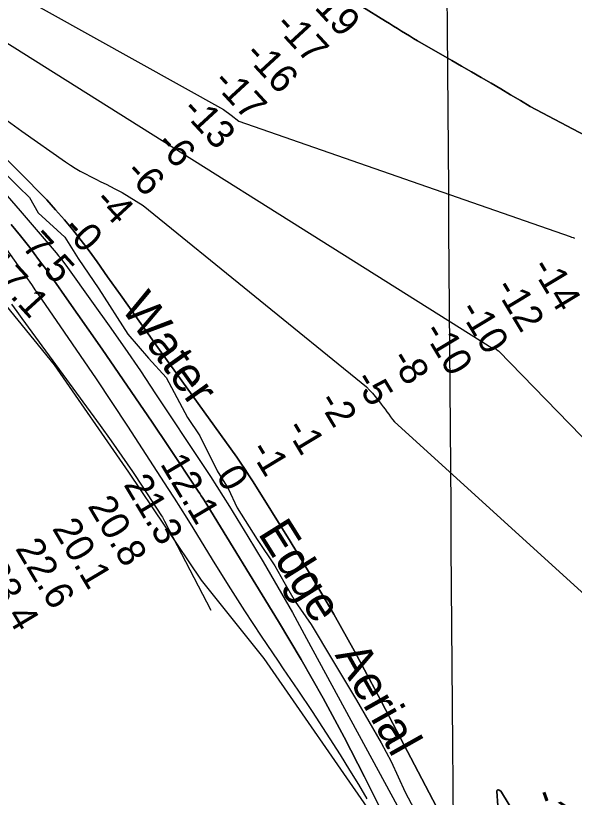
# Model space of a CAD drawing. Extents: x 3540316 to 3578335, y 553172 to 578787.
# Drawn here: x 3548726 to 3550058, y 561708 to 563573 of the extents above; entities that cross this region are included whole.
import ezdxf

# ---------------------------------------------------------------- set-up
doc = ezdxf.new("R2010")
doc.units = 0
for name, color, linetype in [('V-GRID-MAJR', 7, 'Continuous'), ('V-RIVR-EDGE', 7, 'Continuous'), ('V-RIVR-IDEN', 7, 'Continuous'), ('V-RIVR-RANG', 7, 'Continuous'), ('V-SITE-VEGE', 7, 'Continuous'), ('V-TOPO-DPTH', 7, 'Continuous'), ('V-TOPO-MINR', 7, 'Continuous'), ('V-TOPO-WATR', 7, 'Continuous')]:
    doc.layers.add(name, color=color, linetype=linetype)

msp = doc.modelspace()

# ---------------------------------------------------------------- linework, layer by layer
at = {"layer": 'V-GRID-MAJR'}
msp.add_spline([(3549793, 558613.9), (3549748.1, 564672.9), (3549703.1, 570733.8), (3549658.2, 576794.8), (3549658.2, 576796.7)], degree=3, dxfattribs=at)
at = {"layer": 'V-RIVR-EDGE'}
msp.add_lwpolyline([(3548687.7, 563209.2), (3548733.3, 563164.1), (3548759.6, 563138.8), (3548780.5, 563102.7), (3548844, 563044.3), (3548875.1, 562993.8), (3548924.8, 562921.1), (3548994.1, 562812.8), (3549043.2, 562755.7), (3549085.1, 562709.4), (3549136.5, 562614.4), (3549165.2, 562570.5), (3549207, 562486.9), (3549232.8, 562444.9), (3549254.8, 562398.6), (3549302.1, 562322.8), (3549344, 562260.3), (3549366.1, 562221.8), (3549393, 562174.9), (3549430.7, 562120.2), (3549482.1, 562034.8), (3549538.9, 561939.8), (3549598.1, 561838.2), (3549622, 561793.1), (3549655.4, 561719.8), (3549704.4, 561627.2)], dxfattribs=at)
at = {"layer": 'V-SITE-VEGE'}
for p, q in [((3548640.5, 562958.2), (3548817.9, 562739.5)), ((3548817.9, 562739.5), (3548995.5, 562483.8)), ((3548995.5, 562483.8), (3549168.5, 562225.8)), ((3549168.5, 562225.8), (3549317.9, 562039.3)), ((3549317.9, 562039.3), (3549589, 561647.7))]:
    msp.add_line(p, q, dxfattribs=at)
at = {"layer": 'V-TOPO-DPTH'}
for points in [[(3550361.8, 563140.8), (3549952.7, 563355.9), (3549929.6, 563370.1), (3549906.5, 563384.1), (3549883.2, 563398), (3549859.9, 563411.8), (3549836.5, 563425.5), (3549813.1, 563439.1), (3549789.6, 563452.7), (3549766.2, 563466.2), (3549684.8, 563513), (3549675, 563518.7), (3549665.3, 563524.4), (3549655.7, 563530.2), (3549646.1, 563536.1), (3549636.5, 563542), (3549626.9, 563548), (3549617.3, 563553.9), (3549607.8, 563559.8), (3549551.6, 563594.6)], [(3549551.6, 563594.6), (3549607.8, 563559.8), (3549617.3, 563553.9), (3549626.9, 563548), (3549636.5, 563542), (3549646.1, 563536.1), (3549655.7, 563530.2), (3549665.3, 563524.4), (3549675, 563518.7), (3549684.8, 563513), (3549766.2, 563466.2), (3549789.6, 563452.7), (3549813.1, 563439.1), (3549836.5, 563425.5), (3549859.9, 563411.8), (3549883.2, 563398), (3549906.5, 563384.1), (3549929.6, 563370.1), (3549952.7, 563355.9), (3550361.8, 563140.8)], [(3548667.8, 563531.3), (3549862, 562780.5), (3549864.1, 562780.2), (3549868.2, 562778.9), (3549872, 562777), (3549873.9, 562775.9), (3549877.4, 562773.4), (3550244.4, 562395.4)], [(3548667.8, 563531.3), (3549862, 562780.5), (3549864.1, 562780.2), (3549868.2, 562778.9), (3549872, 562777), (3549873.9, 562775.9), (3549877.4, 562773.4), (3550244.4, 562395.4)], [(3549747.4, 561652), (3549581.8, 561967.8), (3549533.9, 562056.8), (3549484.6, 562145.1), (3549433.4, 562232.3), (3549381, 562318.7), (3549292.8, 562460.4), (3549283.3, 562475.3), (3549273.6, 562490.2), (3549263.6, 562504.8), (3549253.4, 562519.3), (3549069.6, 562775.6), (3549038.4, 562819.2), (3549007.4, 562862.7), (3548976.4, 562906.4), (3548945.6, 562950.1), (3548920.5, 562985.8), (3548901.9, 563011.5), (3548882.8, 563036.7), (3548863, 563061.5), (3548842.7, 563085.8), (3548821.7, 563109.6), (3548800.5, 563133.1), (3548778.7, 563156.1), (3548756.5, 563178.8), (3548522.1, 563413.1)], [(3548522.1, 563413.1), (3548756.5, 563178.8), (3548778.7, 563156.1), (3548800.5, 563133.1), (3548821.7, 563109.6), (3548842.7, 563085.8), (3548863, 563061.5), (3548882.8, 563036.7), (3548901.9, 563011.5), (3548920.5, 562985.8), (3548945.6, 562950.1), (3548976.4, 562906.4), (3549007.4, 562862.7), (3549038.4, 562819.2), (3549069.6, 562775.6), (3549253.4, 562519.3), (3549263.6, 562504.8), (3549273.6, 562490.2), (3549283.3, 562475.3), (3549292.8, 562460.4), (3549381, 562318.7), (3549433.4, 562232.3), (3549484.6, 562145.1), (3549533.9, 562056.8), (3549581.8, 561967.8), (3549747.4, 561652)], [(3549640.5, 561591.2), (3549558.2, 561757), (3549509.9, 561851.3), (3549459.8, 561944.7), (3549407.3, 562036.6), (3549353.1, 562127.7), (3549175.9, 562416.5), (3549172.5, 562422), (3549169, 562427.5), (3549165.5, 562433), (3549161.9, 562438.5), (3549091, 562544.7), (3549051.8, 562603.1), (3549012.4, 562661.3), (3548972.6, 562719.3), (3548932.5, 562777.2), (3548843.2, 562905.4), (3548822.8, 562934.2), (3548802.2, 562962.9), (3548781.3, 562991.3), (3548760.1, 563019.5), (3548738.3, 563047.3), (3548716.1, 563074.7)], [(3549913.8, 561671.4), (3549884.4, 561720.3), (3549883, 561722.2), (3549879.5, 561724.9), (3549877.4, 561725.8), (3549875.7, 561725.8), (3549874.4, 561725.3), (3549873.2, 561722.5), (3549876.1, 561687.9)], [(3549876.1, 561687.9), (3549873.2, 561722.5), (3549874.4, 561725.3), (3549875.7, 561725.8), (3549877.4, 561725.8), (3549879.5, 561724.9), (3549883, 561722.2), (3549884.4, 561720.3), (3549913.8, 561671.4)]]:
    msp.add_lwpolyline(points, dxfattribs=at)
at = {"layer": 'V-TOPO-MINR'}
for points in [[(3548700.5, 563640), (3549222.3, 563349.2), (3549240.4, 563335.4), (3549258.3, 563321.4), (3550048.2, 563045.7), (3550051.7, 563044.4), (3550055.2, 563043.2), (3550058.6, 563041.8)], [(3549551.6, 563594.6), (3549607.8, 563559.8), (3549617.3, 563553.9), (3549626.9, 563548), (3549636.5, 563542), (3549646.1, 563536.1), (3549655.7, 563530.2), (3549665.3, 563524.4), (3549675, 563518.7), (3549684.8, 563513), (3549766.2, 563466.2), (3549789.6, 563452.7), (3549813.1, 563439.1), (3549836.5, 563425.5), (3549859.9, 563411.8), (3549883.2, 563398), (3549906.5, 563384.1), (3549929.6, 563370.1), (3549952.7, 563355.9), (3550361.8, 563140.8)], [(3548667.8, 563531.3), (3549862, 562780.5), (3549864.1, 562780.2), (3549868.2, 562778.9), (3549872, 562777), (3549873.9, 562775.9), (3549877.4, 562773.4), (3550244.4, 562395.4)], [(3548706.2, 563322.6), (3548741, 563297.2), (3548845.4, 563224), (3548856.9, 563216.3), (3548868.6, 563208.9), (3548880.6, 563202.1), (3548892.8, 563195.6), (3548905.1, 563189.3), (3548917.5, 563183.1), (3548929.8, 563176.8), (3548942.1, 563170.5), (3548962.7, 563160), (3548980.1, 563150.7), (3548997.2, 563141), (3549014, 563130.6), (3549030.5, 563119.9), (3549563.1, 562687), (3549570.1, 562679.5), (3549576.9, 562671.8), (3549583.6, 562664), (3549590, 562656.1), (3549593.5, 562651.7), (3549598.1, 562645.8), (3549602.7, 562639.9), (3549607.2, 562633.8), (3549611.6, 562627.8), (3549616, 562621.7), (3549620.4, 562615.7), (3549624.9, 562609.7), (3549629.5, 562603.7), (3550135.5, 562143.6)], [(3548695.5, 563155.1), (3548737.3, 563106.9), (3548822.9, 563006.8), (3548828.8, 562999.7), (3548834.6, 562992.5), (3548840.3, 562985.1), (3548845.8, 562977.7), (3548911.4, 562886.3), (3548949.3, 562832.9), (3548986.8, 562779.2), (3549023.7, 562725.1), (3549060.2, 562670.7), (3549175.2, 562497.2), (3549190.7, 562473.5), (3549206.1, 562449.7), (3549221.2, 562425.8), (3549236.1, 562401.7), (3549280, 562330.3), (3549316.2, 562270.1), (3549351.8, 562209.6), (3549386.3, 562148.5), (3549420.2, 562087), (3549665.8, 561632.5)], [(3548608, 563151.7), (3548751.4, 562949), (3548758.5, 562939.1), (3548765.5, 562929.1), (3548772.4, 562919.1), (3548779.4, 562909.1), (3548842.4, 562818), (3548880.6, 562762.3), (3548918.4, 562706.4), (3548955.8, 562650.1), (3548992.9, 562593.6), (3549089.6, 562445), (3549104.7, 562421.6), (3549119.7, 562398), (3549134.5, 562374.3), (3549149.2, 562350.5), (3549195.2, 562275), (3549233.3, 562213.8), (3549272, 562152.9), (3549311.7, 562092.7), (3549352, 562032.9), (3549364.3, 562014.8), (3549398.9, 561963.8), (3549433, 561912.6), (3549466.5, 561861), (3549499.7, 561809.1), (3549522.7, 561772.8), (3549543.5, 561738.6), (3549563.7, 561704)], [(3548716.1, 563074.7), (3548738.3, 563047.3), (3548760.1, 563019.5), (3548781.3, 562991.3), (3548802.2, 562962.9), (3548822.8, 562934.2), (3548843.2, 562905.4), (3548932.5, 562777.2), (3548972.6, 562719.3), (3549012.4, 562661.3), (3549051.8, 562603.1), (3549091, 562544.7), (3549161.9, 562438.5), (3549165.5, 562433), (3549169, 562427.5), (3549172.5, 562422), (3549175.9, 562416.5), (3549353.1, 562127.7), (3549407.3, 562036.6), (3549459.8, 561944.7), (3549509.9, 561851.3), (3549558.2, 561757), (3549640.5, 561591.2)], [(3548716.8, 562884.5), (3548729, 562867.4), (3548741.4, 562850.4), (3548927.8, 562594.9), (3548953.9, 562558.7), (3548979.6, 562522.1), (3549004.7, 562485.2), (3549029.4, 562448), (3549074.3, 562379.1), (3549076.2, 562376.1), (3549078.1, 562373.1), (3549079.8, 562370), (3549081.5, 562366.8), (3549191.7, 562154.5)]]:
    msp.add_lwpolyline(points, dxfattribs=at)
at = {"layer": 'V-TOPO-WATR'}
for points in [[(3548522.1, 563413.1), (3548756.5, 563178.8), (3548778.7, 563156.1), (3548800.5, 563133.1), (3548821.7, 563109.6), (3548842.7, 563085.8), (3548863, 563061.5), (3548882.8, 563036.7), (3548901.9, 563011.5), (3548920.5, 562985.8), (3548945.6, 562950.1), (3548976.4, 562906.4), (3549007.4, 562862.7), (3549038.4, 562819.2), (3549069.6, 562775.6), (3549253.4, 562519.3), (3549263.6, 562504.8), (3549273.6, 562490.2), (3549283.3, 562475.3), (3549292.8, 562460.4), (3549381, 562318.7), (3549433.4, 562232.3), (3549484.6, 562145.1), (3549533.9, 562056.8), (3549581.8, 561967.8), (3549747.4, 561652)], [(3549876.1, 561687.9), (3549873.2, 561722.5), (3549874.4, 561725.3), (3549875.7, 561725.8), (3549877.4, 561725.8), (3549879.5, 561724.9), (3549883, 561722.2), (3549884.4, 561720.3), (3549913.8, 561671.4)]]:
    msp.add_lwpolyline(points, dxfattribs=at)

# ---------------------------------------------------------------- texts
at = {"layer": 'V-RIVR-IDEN'}
for s, rotation, p in [('Water', 305.4415, (3548975.3, 562875.9)), ('Edge', 302.0402, (3549302.7, 562337.6)), ('Aerial', 299.3813, (3549486.5, 562047.4))]:
    msp.add_text(s, height=83, rotation=rotation, dxfattribs=at).set_placement(p)
at = {"layer": 'V-RIVR-RANG'}
for s, rotation, p in [('-19', 312.6426, (3549416.6, 563612.9)), ('-17', 312.6426, (3549340.9, 563547.5)), ('-16', 312.6426, (3549268.9, 563478)), ('-17', 312.6426, (3549193.4, 563412.4)), ('-13', 312.6426, (3549119.3, 563345.2)), ('-6', 312.6426, (3549058.1, 563264.1)), ('-6', 312.6426, (3548984.4, 563196.5)), ('-4', 312.6426, (3548910.8, 563128.7)), ('-0', 312.6426, (3548836.4, 563062)), ('7.5', 312.3583, (3548738.9, 563020.8)), ('17.1', 312.3583, (3548644.4, 562976.1)), ('-14', 301.0706, (3549953.8, 562972.7)), ('-12', 301.0706, (3549866.5, 562923.8)), ('-10', 301.0706, (3549781.7, 562870.8)), ('-10', 301.0706, (3549695.9, 562819.4)), ('-8', 301.0706, (3549618.2, 562754.7)), ('-5', 301.0706, (3549531.8, 562704.2)), ('-2', 301.0706, (3549445.5, 562653.7)), ('-1', 301.0706, (3549368.3, 562588.1)), ('-1', 301.0706, (3549282.5, 562536.7)), ('12.1', 300.7883, (3549069.6, 562503.7)), ('0', 301.0706, (3549202.7, 562475.3)), ('21.3', 300.7883, (3548982.6, 562454.3)), ('20.8', 300.7883, (3548896.8, 562402.9)), ('20.1', 300.7883, (3548812.2, 562349.5)), ('22.6', 300.7883, (3548724.3, 562301.7)), ('23.4', 300.7883, (3548639.5, 562248.7)), ('-1', 289.8741, (3549960.1, 561714.9))]:
    msp.add_text(s, height=67, rotation=rotation, dxfattribs=at).set_placement(p)

doc.saveas('drawing.dxf')
